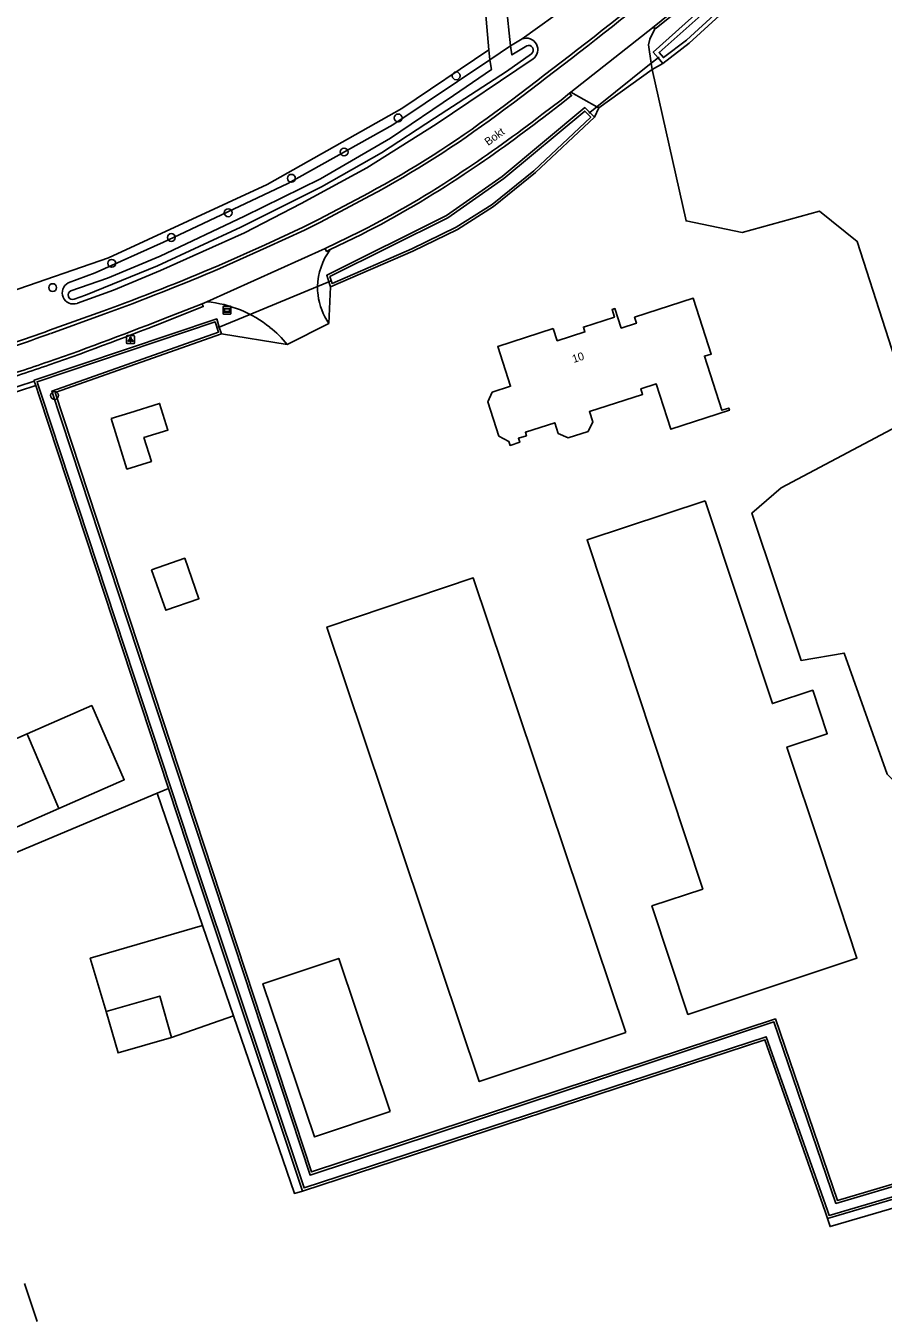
# Model space of a CAD drawing. Extents: x 162515 to 163909, y 388494 to 389773.
# Drawn here: x 163202.2 to 163309.4, y 388872.2 to 389033.6 of the extents above; entities that cross this region are included whole.
import ezdxf

# ---------------------------------------------------------------- set-up
doc = ezdxf.new("R2010")
doc.units = 0
for name, color, linetype in [('IMGEO_Berm_groen', 7, 'Continuous'), ('IMGEO_Boom', 7, 'Continuous'), ('IMGEO_Duiker', 7, 'Continuous'), ('IMGEO_Erf', 7, 'Continuous'), ('IMGEO_Grasland_agrarisch', 7, 'Continuous'), ('IMGEO_Grasland_overig', 7, 'Continuous'), ('IMGEO_Haag', 7, 'Continuous'), ('IMGEO_Lichtpunt', 7, 'Continuous'), ('IMGEO_Loofbos', 7, 'Continuous'), ('IMGEO_Openbare_ruimte_label', 7, 'Continuous'), ('IMGEO_Pand', 7, 'Continuous'), ('IMGEO_Pand_nummerreeks', 7, 'Continuous'), ('IMGEO_Rijbaan_lokaal_gesloten', 7, 'Continuous'), ('IMGEO_Rijbaan_lokaal_halfverhard', 7, 'Continuous'), ('IMGEO_Rijbaan_lokaal_open', 7, 'Continuous'), ('IMGEO_Verklikker', 7, 'Continuous'), ('IMGEO_Waterloop', 7, 'Continuous')]:
    doc.layers.add(name, color=color, linetype=linetype)

msp = doc.modelspace()

# ---------------------------------------------------------------- linework, layer by layer
at = {"layer": 'IMGEO_Berm_groen'}
msp.add_lwpolyline([(163202.02, 388876.51), (163203.59, 388871.75)], dxfattribs=at)
at = {"layer": 'IMGEO_Boom'}
for centre in [(163255.98, 389027.4), (163248.73, 389022.14), (163241.97, 389017.88), (163235.38, 389014.6), (163227.48, 389010.29), (163220.37, 389007.2), (163212.92, 389003.97), (163205.54, 389000.94), (163205.77, 388987.46)]:
    msp.add_circle(centre, 0.489, dxfattribs=at)
at = {"layer": 'IMGEO_Duiker'}
for points in [[(163272.58, 389022.73), (163272.68, 389022.81), (163273.58, 389023.53), (163280.37, 389028.98), (163281.21, 389029.66), (163281.35, 389029.77)], [(163226.24, 388995.96), (163226.37, 388996.01), (163230.09, 388997.55), (163238.65, 389001.09), (163240.06, 389001.67), (163240.28, 389001.76)]]:
    msp.add_lwpolyline(points, dxfattribs=at)
at = {"layer": 'IMGEO_Erf'}
for points in [[(163264.23, 389032.02), (163262.76, 389031.16)], [(163273.26, 389022.24), (163265.91, 389015.3), (163260.65, 389011.08), (163256.15, 389008.21), (163250.55, 389005.49), (163240.28, 389001.03)], [(163203.24, 388989.26), (163203.21, 388989.36), (163226.04, 388997.02), (163226.37, 388996.01), (163226.64, 388995.18)], [(163362.05, 388904.15), (163360.59, 388903.73), (163351.03, 388900.97), (163350.13, 388900.73), (163348.74, 388900.22), (163303.64, 388886.88), (163295.89, 388909.55), (163237.9, 388890.43), (163205.83, 388987.83), (163226.64, 388995.18)], [(163226.64, 388995.18), (163234.85, 388993.82)], [(163220.03, 388938.34), (163203.9, 388987.27), (163203.43, 388988.69)]]:
    msp.add_lwpolyline(points, dxfattribs=at)
at = {"layer": 'IMGEO_Grasland_agrarisch'}
for points in [[(163303.82, 389048.61), (163303.6, 389048.41), (163285.1, 389031.47), (163281.81, 389028.95)], [(163362.05, 388904.15), (163355.41, 388924.72), (163354.01, 388929.19), (163350.65, 388931.58), (163341.32, 388928.28), (163332.12, 388924.83), (163319.85, 388920.88), (163315.1, 388934.86), (163309.87, 388940.12), (163304.47, 388955.27), (163299.09, 388954.35), (163292.95, 388972.77), (163296.59, 388975.91), (163313.19, 388984.7), (163306.1, 389006.71), (163301.39, 389010.47), (163291.73, 389007.83), (163284.72, 389009.28), (163280.49, 389028.19)], [(163186.47, 388924.27), (163218.62, 388937.76)], [(163212.23, 388910.49), (163210.23, 388917.13), (163224.28, 388921.24)], [(163228.15, 388909.94), (163220.41, 388907.22)], [(163236.77, 388888.05), (163294.57, 388906.95), (163302.1, 388885.51), (163302.4, 388884.63)]]:
    msp.add_lwpolyline(points, dxfattribs=at)
at = {"layer": 'IMGEO_Grasland_overig'}
for points in [[(163281.81, 389028.95), (163281.21, 389029.66), (163280.62, 389030.35), (163298.17, 389046.16), (163302.23, 389050.2), (163303.06, 389049.36), (163303.82, 389048.61)], [(163280.49, 389028.19), (163281.81, 389028.95)], [(163240.28, 389001.03), (163240.06, 389001.67), (163239.8, 389002.48), (163254.75, 389009.95), (163261.73, 389014.84), (163272.07, 389023.43), (163272.68, 389022.81), (163273.26, 389022.24)], [(163273.26, 389022.24), (163273.81, 389023.41)], [(163240.06, 388996.44), (163240.28, 389001.03)], [(163501.84, 388971.28), (163500.6, 388970.68), (163498.6, 388970.32), (163496.72, 388969.98), (163500.85, 388949.57), (163391.99, 388916.5), (163391.33, 388909.48), (163302.72, 388883.6), (163302.4, 388884.63)], [(163218.62, 388937.76), (163220.03, 388938.34)], [(163224.28, 388921.24), (163218.62, 388937.76)], [(163220.03, 388938.34), (163223.62, 388927.46), (163236.77, 388888.05)], [(163228.15, 388909.94), (163224.28, 388921.24)], [(163236.77, 388888.05), (163235.76, 388887.75), (163228.15, 388909.94)], [(163302.4, 388884.63), (163389.1, 388910.15)]]:
    msp.add_lwpolyline(points, dxfattribs=at)
at = {"layer": 'IMGEO_Haag'}
for points in [[(163203.43, 388988.69), (163197.26, 388986.69), (163197.07, 388987.26), (163203.24, 388989.26)], [(163203.24, 388989.26), (163203.36, 388988.9), (163203.43, 388988.69)]]:
    msp.add_lwpolyline(points, dxfattribs=at)
at = {"layer": 'IMGEO_Lichtpunt'}
for p, q in [((163214.77, 388994.85), (163214.77, 388994.04)), ((163214.77, 388994.85), (163214.77, 388994.04)), ((163215.67, 388994.94), (163214.87, 388994.94)), ((163215.67, 388994.94), (163214.87, 388994.94)), ((163214.87, 388993.95), (163215.67, 388993.95)), ((163214.87, 388993.95), (163215.67, 388993.95)), ((163215.77, 388994.04), (163215.77, 388994.85)), ((163215.77, 388994.04), (163215.77, 388994.85))]:
    msp.add_line(p, q, dxfattribs=at)
for points in [[(163215.15, 388994.51), (163215.19, 388994.49), (163215, 388994.22), (163214.96, 388994.25), (163215.15, 388994.51)], [(163215.25, 388994.47), (163215.3, 388994.47), (163215.3, 388994.14), (163215.25, 388994.14), (163215.25, 388994.47)], [(163215.36, 388994.49), (163215.4, 388994.51), (163215.58, 388994.25), (163215.55, 388994.22), (163215.36, 388994.49)]]:
    msp.add_lwpolyline(points, dxfattribs=at)
msp.add_circle((163215.27, 388994.65), 0.0994, dxfattribs=at)
for centre, start, end in [((163214.87, 388994.85), 90, 180), ((163214.87, 388994.85), 90, 180), ((163214.87, 388994.04), 180, 270), ((163214.87, 388994.04), 180, 270), ((163215.67, 388994.85), 0, 90), ((163215.67, 388994.85), 0, 90), ((163215.67, 388994.04), 270, 0), ((163215.67, 388994.04), 270, 360)]:
    msp.add_arc(centre, 0.0946, start, end, dxfattribs=at)
at = {"layer": 'IMGEO_Loofbos'}
for points in [[(163260.08, 389030.66), (163249.17, 389023.32), (163232.36, 389013.8), (163212.52, 389004.67), (163200.21, 389000.42), (163167.6, 388990.42), (163167.95, 388999.89), (163170.28, 389025.02), (163173.68, 389061.1), (163174.69, 389069.45), (163185.76, 389072.18), (163199.48, 389075.57), (163223.18, 389081.54), (163255.47, 389089.06)], [(163270.26, 389036.35), (163264.23, 389032.02)], [(163207.47, 389001.54), (163210.83, 389002.8), (163219.38, 389006.61), (163221.36, 389007.54), (163234.95, 389013.95), (163248.07, 389021.29), (163260.2, 389029.4)], [(163265.6, 389029.51), (163253.49, 389021.37), (163244.79, 389015.89), (163236.6, 389011.45), (163229.51, 389007.79), (163224.29, 389005.43), (163219.03, 389003.06), (163213.15, 389000.6), (163208.65, 388998.99), (163208.6, 388998.97)]]:
    msp.add_lwpolyline(points, dxfattribs=at)
for centre, radius, start, end in [((163264.75, 389030.67), 1.44, 305.8993, 111.4524), ((163208.15, 389000.3), 1.41, 118.7932, 288.6267)]:
    msp.add_arc(centre, radius, start, end, dxfattribs=at)
at = {"layer": 'IMGEO_Pand'}
for points in [[(163268.12, 388995.83), (163268.61, 388994.29), (163272.08, 388995.41), (163271.89, 388996.01), (163275.76, 388997.26), (163275.46, 388998.2), (163275.83, 388998.32), (163276.61, 388995.87), (163278.52, 388996.49), (163278.28, 388997.23), (163285.61, 388999.6), (163287.15, 388994.84), (163287.86, 388992.64), (163287.01, 388992.37), (163289.2, 388985.61), (163290.05, 388985.89), (163290.14, 388985.61), (163282.82, 388983.24), (163280.99, 388988.91), (163279.07, 388988.29), (163279.29, 388987.6), (163272.64, 388985.45), (163273.05, 388984.18), (163272.46, 388982.97), (163269.96, 388982.16), (163268.74, 388982.71), (163268.3, 388984.05), (163264.64, 388982.86), (163264.77, 388982.43), (163263.76, 388982.11), (163263.92, 388981.61), (163262.71, 388981.22), (163262.55, 388981.71), (163261.31, 388982.38), (163259.92, 388986.67), (163260.49, 388987.87), (163262.78, 388988.61), (163261.17, 388993.58), (163268.12, 388995.83)], [(163212.84, 388984.56), (163214.81, 388978.25), (163217.89, 388979.22), (163216.95, 388982.2), (163219.95, 388983.14), (163218.91, 388986.46), (163215.2, 388985.3), (163212.84, 388984.56)], [(163287.12, 388974.31), (163295.52, 388948.96), (163300.55, 388950.63), (163302.36, 388945.19), (163297.33, 388943.52), (163301.59, 388930.68), (163306.08, 388917.13), (163284.94, 388910.12), (163280.45, 388923.67), (163286.81, 388925.78), (163272.34, 388969.41), (163287.12, 388974.31)], [(163217.9, 388965.66), (163219.67, 388960.61), (163223.81, 388962.05), (163222.04, 388967.11), (163217.9, 388965.66)], [(163277.17, 388907.86), (163258.87, 388901.72), (163239.82, 388958.52), (163258.12, 388964.66), (163277.17, 388907.86)], [(163202.34, 388945.16), (163210.43, 388948.71), (163214.49, 388939.45), (163206.32, 388935.86)], [(163206.32, 388935.86), (163196.07, 388931.36), (163195.05, 388933.68), (163191.62, 388932.17), (163188.57, 388939.12), (163202.34, 388945.16)], [(163202.34, 388945.16), (163202.37, 388945.06), (163206.32, 388935.86)], [(163247.73, 388897.98), (163238.25, 388894.8), (163231.83, 388913.94), (163241.31, 388917.12), (163247.73, 388897.98)], [(163212.23, 388910.49), (163218.92, 388912.41), (163220.41, 388907.22)], [(163220.41, 388907.22), (163213.71, 388905.31), (163212.23, 388910.49)]]:
    msp.add_lwpolyline(points, dxfattribs=at)
at = {"layer": 'IMGEO_Rijbaan_lokaal_gesloten'}
for points in [[(163285.74, 389037.65), (163280.51, 389033.41)], [(163270.32, 389025.37), (163280.51, 389033.41)], [(163270.16, 389025.24), (163269.09, 389024.37), (163266.69, 389022.55)], [(163270.32, 389025.37), (163270.16, 389025.24)], [(163226.44, 389003.34), (163232.26, 389005.94), (163237.01, 389008.1), (163239.03, 389009.12), (163245.2, 389012.4)], [(163243.98, 389007.93), (163239.6, 389005.82)], [(163239.6, 389005.82), (163224.82, 388999.16)], [(163239.6, 389005.82), (163239.77, 389005.46), (163240.24, 389005.69)], [(163224.22, 388998.93), (163220.13, 388997.34)], [(163224.82, 388999.16), (163224.22, 388998.93)], [(163205.29, 388995.22), (163211.93, 388997.6)], [(163234.85, 388993.82), (163240.06, 388996.44)]]:
    msp.add_lwpolyline(points, dxfattribs=at)
for centre, radius, start, end in [((162905.81, 389500.6), 595.64, 306.61225, 308.61552), ((163184.8, 389124.74), 127.55, 298.2657, 306.7141), ((163154.67, 389168.3), 183.82, 303.7315, 307.5432), ((163186.83, 389119.96), 125.76, 297.0249, 303.7759), ((163246.56, 389000.94), 7.9, 143.099, 178.9282), ((163115.64, 389262.68), 282.02, 289.9642, 293.1356), ((163246.49, 389000.95), 7.84, 178.9475, 186.9346), ((163223.44, 388984.43), 14.8, 51.26, 84.6211), ((163246.52, 389000.93), 7.86, 186.7671, 214.8026), ((163091.95, 389316.67), 344.1, 289.1765, 291.8701), ((163224.81, 388985.9), 12.79, 38.2604, 51.926), ((163153.6, 389134.53), 148.59, 286.3823, 290.3539), ((163153.1, 389139.28), 156.46, 286.6769, 289.363)]:
    msp.add_arc(centre, radius, start, end, dxfattribs=at)
at = {"layer": 'IMGEO_Rijbaan_lokaal_halfverhard'}
for points in [[(163280.85, 389033.37), (163280.98, 389033.35), (163286.08, 389037.46)], [(163266.93, 389022.23), (163269.33, 389024.05), (163270.41, 389024.93), (163270.16, 389025.24)], [(163245.01, 389012.75), (163238.85, 389009.48), (163236.84, 389008.47), (163232.1, 389006.3), (163226.29, 389003.71)], [(163240.24, 389005.69), (163244.16, 389007.58)], [(163220.27, 388996.97), (163224.37, 388998.56), (163224.22, 388998.93)], [(163211.79, 388997.98), (163205.15, 388995.6)]]:
    msp.add_lwpolyline(points, dxfattribs=at)
for centre, radius, start, end in [((162908.13, 389497.57), 591.42, 306.6068, 308.62304), ((163184.86, 389124.63), 127.02, 298.2632, 306.7191), ((163154.85, 389168.07), 183.93, 303.7255, 307.5434), ((163187.13, 389119.45), 125.56, 297.0108, 303.7936), ((163115.53, 389262.97), 281.93, 289.965, 293.1326), ((163091.45, 389317.94), 345.86, 289.1846, 291.8679), ((163153.78, 389134.02), 147.64, 286.3724, 290.36), ((163152.69, 389140.62), 158.27, 286.6836, 289.3425)]:
    msp.add_arc(centre, radius, start, end, dxfattribs=at)
at = {"layer": 'IMGEO_Rijbaan_lokaal_open'}
for points in [[(163280.85, 389033.37), (163280.19, 389031.97), (163280.04, 389031.28), (163280.37, 389028.98), (163280.49, 389028.19)], [(163280.51, 389033.41), (163280.85, 389033.37)], [(163280.49, 389028.19), (163273.81, 389023.41)], [(163273.81, 389023.41), (163273.58, 389023.53), (163270.32, 389025.37)]]:
    msp.add_lwpolyline(points, dxfattribs=at)
at = {"layer": 'IMGEO_Verklikker'}
for p, q in [((163226.84, 388997.71), (163226.84, 388998.51)), ((163226.84, 388998.51), (163226.84, 388997.71)), ((163226.94, 388998.61), (163227.72, 388998.61)), ((163227.72, 388998.61), (163226.94, 388998.61)), ((163227.82, 388998.51), (163227.82, 388997.71)), ((163227.82, 388997.71), (163227.82, 388998.51)), ((163227.72, 388997.61), (163226.94, 388997.61)), ((163226.94, 388997.61), (163227.72, 388997.61))]:
    msp.add_line(p, q, dxfattribs=at)
for points in [[(163226.94, 388998.34), (163227.72, 388998.34), (163227.72, 388997.88), (163226.94, 388997.88), (163226.94, 388998.34)], [(163227, 388998.28), (163227, 388997.94), (163227.66, 388997.94), (163227.66, 388998.28), (163227, 388998.28)]]:
    msp.add_lwpolyline(points, dxfattribs=at)
for centre, start, end in [((163226.94, 388998.51), 90, 180), ((163226.94, 388998.51), 90, 180), ((163227.72, 388998.51), 0, 90), ((163227.72, 388998.51), 360, 90), ((163226.94, 388997.71), 180, 270), ((163226.94, 388997.71), 180, 270), ((163227.72, 388997.71), 270, 0), ((163227.72, 388997.71), 270, 0)]:
    msp.add_arc(centre, 0.1, start, end, dxfattribs=at)
at = {"layer": 'IMGEO_Waterloop'}
for points in [[(163257.73, 389091.22), (163256.92, 389091), (163260.61, 389051.86), (163262.76, 389031.16)], [(163260.08, 389030.66), (163258.23, 389051.72), (163256.49, 389076.52), (163255.47, 389089.06)], [(163303.06, 389048.63), (163284.76, 389031.87), (163281.89, 389029.67), (163281.35, 389030.3), (163286.61, 389034.99), (163298.52, 389045.78), (163302.23, 389049.46), (163303.06, 389048.63)], [(163262.76, 389031.16), (163260.2, 389029.4)], [(163262.76, 389031.16), (163262.94, 389030.02), (163264.8, 389031.15)], [(163207.81, 389000.54), (163212.38, 389002.11), (163218.96, 389004.88), (163229.5, 389009.85), (163239.02, 389014.52), (163247.75, 389019.62), (163255.64, 389024.93), (163260.39, 389028.19), (163260.2, 389029.4)], [(163265.39, 389030.13), (163262.26, 389027.93), (163253.29, 389022.1), (163246.63, 389017.79), (163239.13, 389013.53), (163229.06, 389008.49), (163218.66, 389003.65), (163209.64, 389000), (163208.22, 388999.5)], [(163260.2, 389029.4), (163260.08, 389030.66)], [(163272.46, 389022.58), (163272.8, 389022.24), (163265.7, 389015.54), (163260.46, 389011.34), (163255.99, 389008.5), (163250.42, 389005.79), (163240.47, 389001.46), (163240.19, 389002.32), (163254.92, 389009.67), (163261.92, 389014.58), (163272.05, 389022.99), (163272.46, 389022.58)], [(163204.18, 388987.36), (163203.64, 388988.99), (163203.59, 388989.17), (163225.85, 388996.64), (163226.27, 388995.36), (163205.45, 388988.01), (163237.71, 388890.05), (163295.7, 388909.17), (163303.45, 388886.51), (163348.84, 388899.93), (163350.22, 388900.45), (163351.11, 388900.68), (163388.41, 388911.45), (163389.08, 388915.22), (163389.5, 388916.54)], [(163389, 388910.44), (163302.59, 388885), (163302.38, 388885.6), (163294.75, 388907.32), (163236.96, 388888.43), (163223.9, 388927.55), (163220.31, 388938.44), (163204.18, 388987.36)]]:
    msp.add_lwpolyline(points, dxfattribs=at)
for centre, radius, start, end in [((163265.03, 389030.61), 0.592, 307.0488, 112.804), ((163208.02, 389000.02), 0.562, 112.2494, 290.8426)]:
    msp.add_arc(centre, radius, start, end, dxfattribs=at)

# ---------------------------------------------------------------- texts
at = {"layer": 'IMGEO_Openbare_ruimte_label'}
msp.add_text('Bokt', height=1, rotation=36.2508, dxfattribs=at).set_placement((163259.98, 389018.62))
at = {"layer": 'IMGEO_Pand_nummerreeks'}
msp.add_text('10', height=1, rotation=17.9164, dxfattribs=at).set_placement((163270.66, 388991.51))

doc.saveas('drawing.dxf')
